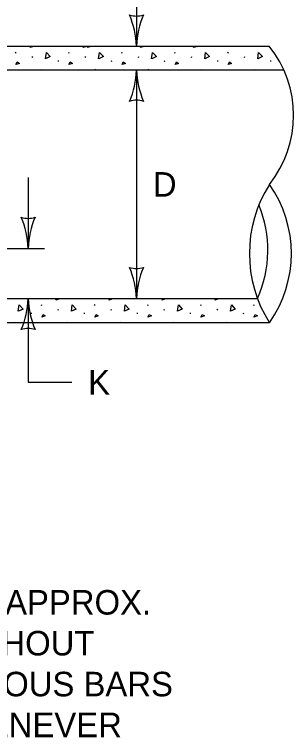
# Model space of a CAD drawing. Extents: x 49991.4 to 50043, y 49987.6 to 50011.4.
# Drawn here: x 50013.274 to 50013.956, y 49996.333 to 49998.102 of the extents above; entities that cross this region are included whole.
import ezdxf

# ---------------------------------------------------------------- set-up
doc = ezdxf.new("R2010")
doc.units = 0
for name, color, linetype in [('Level 1', 7, 'Continuous'), ('Level 2', 7, 'Continuous'), ('Level 3', 7, 'Continuous')]:
    doc.layers.add(name, color=color, linetype=linetype)

msp = doc.modelspace()

# ---------------------------------------------------------------- linework, layer by layer
at = {"layer": 'Level 1'}
for p, q in [((50013.206, 49998.0246), (50013.8966, 49998.0246)), ((50013.2769, 49998.0072), (50013.278, 49998.0096)), ((50013.4066, 49998.0072), (50013.4076, 49998.0096)), ((50013.5362, 49998.0072), (50013.5372, 49998.0096)), ((50013.6658, 49998.0072), (50013.6668, 49998.0096)), ((50013.7954, 49998.0072), (50013.7965, 49998.0096)), ((50013.3174, 49997.9963), (50013.3185, 49997.9987)), ((50013.3808, 49997.9896), (50013.381, 49997.9872)), ((50013.447, 49997.9963), (50013.4481, 49997.9987)), ((50013.5104, 49997.9896), (50013.5107, 49997.9872)), ((50013.5767, 49997.9963), (50013.5777, 49997.9987)), ((50013.64, 49997.9896), (50013.6403, 49997.9872)), ((50013.7063, 49997.9963), (50013.7073, 49997.9987)), ((50013.7696, 49997.9896), (50013.7699, 49997.9872)), ((50013.8359, 49997.9963), (50013.837, 49997.9987)), ((50013.8992, 49997.9896), (50013.8995, 49997.9872)), ((50013.9324, 49997.9654), (50013.1428, 49997.9654)), ((50013.3417, 49997.9654), (50013.3427, 49997.9678)), ((50013.4713, 49997.9654), (50013.4724, 49997.9678)), ((50013.6009, 49997.9654), (50013.602, 49997.9678)), ((50013.7305, 49997.9654), (50013.7316, 49997.9678)), ((50013.8601, 49997.9654), (50013.8612, 49997.9678)), ((50013.1428, 49997.4069), (50013.8675, 49997.4069)), ((50013.3401, 49997.3896), (50013.3412, 49997.392)), ((50013.4698, 49997.3896), (50013.4708, 49997.392)), ((50013.5994, 49997.3896), (50013.6004, 49997.392)), ((50013.729, 49997.3896), (50013.73, 49997.392)), ((50013.8586, 49997.3896), (50013.8597, 49997.392)), ((50013.3144, 49997.372), (50013.3146, 49997.3696)), ((50013.3806, 49997.3787), (50013.3817, 49997.3811)), ((50013.444, 49997.372), (50013.4442, 49997.3696)), ((50013.5102, 49997.3787), (50013.5113, 49997.3811)), ((50013.5736, 49997.372), (50013.5739, 49997.3696)), ((50013.6399, 49997.3787), (50013.6409, 49997.3811)), ((50013.7032, 49997.372), (50013.7035, 49997.3696)), ((50013.7695, 49997.3787), (50013.7705, 49997.3811)), ((50013.8328, 49997.372), (50013.8331, 49997.3696)), ((50013.2753, 49997.3478), (50013.2763, 49997.3502)), ((50013.4049, 49997.3478), (50013.4059, 49997.3502)), ((50013.5345, 49997.3478), (50013.5356, 49997.3502)), ((50013.6641, 49997.3478), (50013.6652, 49997.3502)), ((50013.7937, 49997.3478), (50013.7948, 49997.3502)), ((50013.8966, 49997.3478), (50013.206, 49997.3478))]:
    msp.add_line(p, q, dxfattribs=at)
for points in [[(50013.3122, 49998.0209), (50013.314, 49998.0246)], [(50013.3194, 49998.0246), (50013.3207, 49998.0236), (50013.3122, 49998.0209)], [(50013.4418, 49998.0209), (50013.4436, 49998.0246)], [(50013.449, 49998.0246), (50013.4503, 49998.0236), (50013.4418, 49998.0209)], [(50013.4523, 49998.0209), (50013.454, 49998.0245)], [(50013.4595, 49998.0245), (50013.4608, 49998.0236), (50013.4523, 49998.0209)], [(50013.5819, 49998.0209), (50013.5836, 49998.0245)], [(50013.5892, 49998.0245), (50013.5904, 49998.0236), (50013.5819, 49998.0209)], [(50013.7115, 49998.0209), (50013.7132, 49998.0245)], [(50013.7188, 49998.0245), (50013.72, 49998.0236), (50013.7115, 49998.0209)], [(50013.3498, 49997.9935), (50013.352, 49998.0088), (50013.3615, 49997.9989), (50013.3501, 49997.9936)], [(50013.4795, 49997.9935), (50013.4816, 49998.0088), (50013.4911, 49997.9989), (50013.4797, 49997.9936)], [(50013.6091, 49997.9935), (50013.6112, 49998.0088), (50013.6207, 49997.9989), (50013.6093, 49997.9936)], [(50013.7387, 49997.9935), (50013.7408, 49998.0088), (50013.7503, 49997.9989), (50013.7389, 49997.9936)], [(50013.8683, 49997.9935), (50013.8704, 49998.0088), (50013.8799, 49997.9989), (50013.8685, 49997.9936)], [(50013.2775, 49997.9793), (50013.2807, 49997.9859), (50013.286, 49997.9819), (50013.2775, 49997.9793)], [(50013.4071, 49997.9793), (50013.4103, 49997.9859), (50013.4156, 49997.9819), (50013.4071, 49997.9793)], [(50013.5367, 49997.9793), (50013.5399, 49997.9859), (50013.5452, 49997.9819), (50013.5367, 49997.9793)], [(50013.6663, 49997.9793), (50013.6695, 49997.9859), (50013.6748, 49997.9819), (50013.6663, 49997.9793)], [(50013.7959, 49997.9793), (50013.7991, 49997.9859), (50013.8045, 49997.9819), (50013.7959, 49997.9793)], [(50013.3754, 49997.4033), (50013.3771, 49997.4069)], [(50013.3827, 49997.4069), (50013.3839, 49997.406), (50013.3754, 49997.4033)], [(50013.505, 49997.4033), (50013.5067, 49997.4069)], [(50013.5123, 49997.4069), (50013.5135, 49997.406), (50013.505, 49997.4033)], [(50013.6346, 49997.4033), (50013.6363, 49997.4069)], [(50013.6419, 49997.4069), (50013.6431, 49997.406), (50013.6346, 49997.4033)], [(50013.7642, 49997.4033), (50013.7659, 49997.4069)], [(50013.7715, 49997.4069), (50013.7727, 49997.406), (50013.7642, 49997.4033)], [(50013.2834, 49997.3759), (50013.2855, 49997.3912), (50013.2951, 49997.3813), (50013.2837, 49997.376)], [(50013.413, 49997.3759), (50013.4152, 49997.3912), (50013.4247, 49997.3813), (50013.4133, 49997.376)], [(50013.5427, 49997.3759), (50013.5448, 49997.3912), (50013.5543, 49997.3813), (50013.5429, 49997.376)], [(50013.6723, 49997.3759), (50013.6744, 49997.3912), (50013.6839, 49997.3813), (50013.6725, 49997.376)], [(50013.8019, 49997.3759), (50013.804, 49997.3912), (50013.8135, 49997.3813), (50013.8021, 49997.376)], [(50013.3407, 49997.3617), (50013.3439, 49997.3683), (50013.3492, 49997.3643), (50013.3407, 49997.3617)], [(50013.4703, 49997.3617), (50013.4735, 49997.3683), (50013.4788, 49997.3643), (50013.4703, 49997.3617)], [(50013.5999, 49997.3617), (50013.6031, 49997.3683), (50013.6084, 49997.3643), (50013.5999, 49997.3617)], [(50013.7295, 49997.3617), (50013.7327, 49997.3683), (50013.738, 49997.3643), (50013.7295, 49997.3617)], [(50013.8591, 49997.3617), (50013.8623, 49997.3683), (50013.8677, 49997.3643), (50013.8591, 49997.3617)]]:
    msp.add_lwpolyline(points, dxfattribs=at)
for centre, radius, start, end in [((50013.6839, 49997.8553), 0.2718, 321.5118, 38.5186), ((50014.1655, 49997.517), 0.3176, 147.818, 212.1849), ((50013.6583, 49997.517), 0.2923, 324.6332, 35.3668), ((50013.6061, 49997.5252), 0.287, 335.6613, 22.6629)]:
    msp.add_arc(centre, radius, start, end, dxfattribs=at)
at = {"layer": 'Level 3'}
for p, q in [((50013.5721, 49998.1901), (50013.5721, 49998.0246)), ((50013.5721, 49997.9654), (50013.5721, 49997.4069)), ((50013.3075, 49997.7032), (50013.3075, 49997.5297)), ((50013.1828, 49997.5297), (50013.3475, 49997.5297)), ((50013.3075, 49997.4069), (50013.3075, 49997.202)), ((50013.3075, 49997.202), (50013.4139, 49997.202))]:
    msp.add_line(p, q, dxfattribs=at)
for centre, radius, start, end in [((50013.5721, 49998.1528), 0.0548, 252.1388, 287.8612), ((50013.3394, 49998.0131), 0.233, 2.8273, 22.0772), ((50013.7942, 49998.0155), 0.2223, 157.456, 177.6395), ((50013.35, 49997.9746), 0.2223, 337.456, 357.6395), ((50013.8048, 49997.9769), 0.233, 182.8273, 202.0772), ((50013.5721, 49997.8372), 0.0548, 72.1388, 107.8612), ((50013.3075, 49997.6579), 0.0548, 252.1388, 287.8612), ((50013.0748, 49997.5182), 0.233, 2.8273, 22.0772), ((50013.5296, 49997.5206), 0.2223, 157.456, 177.6395), ((50013.5721, 49997.5351), 0.0548, 252.1388, 287.8612), ((50013.3394, 49997.3954), 0.233, 2.8273, 22.0772), ((50013.7942, 49997.3978), 0.2223, 157.456, 177.6395), ((50013.0854, 49997.4161), 0.2223, 337.456, 357.6395), ((50013.5402, 49997.4184), 0.233, 182.8273, 202.0772), ((50013.3075, 49997.2787), 0.0548, 72.1388, 107.8612)]:
    msp.add_arc(centre, radius, start, end, dxfattribs=at)

# ---------------------------------------------------------------- texts
at = {"layer": 'Level 2'}
for s, p in [('D', (50013.6121, 49997.6562)), ('K', (50013.4539, 49997.172)), ('SPACE REINFORCING BARS APPROX.', (50012.1321, 49996.6338)), ('300 mm EACH WAY THROUGHOUT', (50012.1321, 49996.5338)), ('STRUCTURE.  USE CONTINUOUS BARS', (50012.1321, 49996.4338)), ('IN FLOORS AND WALLS WHENEVER', (50012.1321, 49996.3338))]:
    msp.add_text(s, height=0.06, dxfattribs=at).set_placement(p)

doc.saveas('drawing.dxf')
